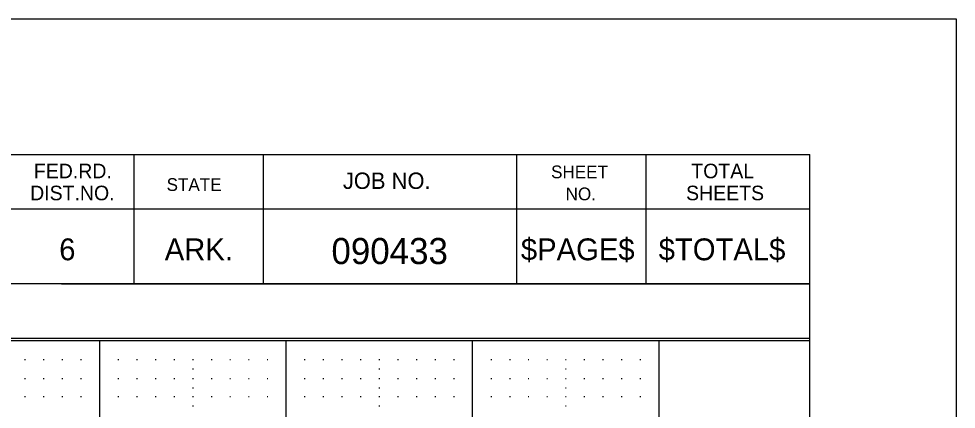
# Model space of a CAD drawing. Extents: x 0 to 34, y 0 to 22.
# Drawn here: x 28.97 to 34, y 19.9 to 22 of the extents above; entities that cross this region are included whole.
import ezdxf

# ---------------------------------------------------------------- set-up
doc = ezdxf.new("R2010")
doc.units = 0
for name, color, linetype in [('Level 1', 7, 'Continuous'), ('Level 4', 7, 'Continuous'), ('Level 5', 7, 'Continuous'), ('Level 63', 7, 'Continuous'), ('R_Border', 7, 'Continuous')]:
    doc.layers.add(name, color=color, linetype=linetype)

msp = doc.modelspace()

# ---------------------------------------------------------------- linework, layer by layer
at = {"layer": 'Level 1'}
for p, q in [((1.597, 21.272), (33.215, 21.272)), ((29.589, 21.2719), (29.589, 20.5779)), ((30.283, 21.2719), (30.283, 20.5779)), ((31.641, 21.2719), (31.641, 20.5779)), ((32.335, 21.2719), (32.335, 20.5779)), ((33.215, 0.726), (33.215, 21.272)), ((33.215, 20.9779), (28.905, 20.9779)), ((33.215, 20.9799), (33.215, 20.9799)), ((33.215, 20.5779), (28.905, 20.5779)), ((29.201, 20.5779), (33.215, 20.5779)), ((33.215, 20.2839), (26.951, 20.2839))]:
    msp.add_line(p, q, dxfattribs=at)
at = {"layer": 'Level 4'}
for p, q in [((33.215, 20.272), (1.597, 20.272)), ((29.406, 1.272), (29.406, 20.272)), ((30.406, 1.272), (30.406, 20.272)), ((31.406, 1.272), (31.406, 20.272)), ((32.406, 1.272), (32.406, 20.272))]:
    msp.add_line(p, q, dxfattribs=at)
at = {"layer": 'Level 5'}
for p, q in [((29.0035, 20.1705), (29.0085, 20.1705)), ((29.1035, 20.1705), (29.1085, 20.1705)), ((29.2035, 20.1705), (29.2085, 20.1705)), ((29.3035, 20.1705), (29.3085, 20.1705)), ((29.5035, 20.1705), (29.5085, 20.1705)), ((29.6035, 20.1705), (29.6085, 20.1705)), ((29.7035, 20.1705), (29.7085, 20.1705)), ((29.8035, 20.1705), (29.8085, 20.1705)), ((29.9035, 20.1705), (29.9085, 20.1705)), ((30.0035, 20.1705), (30.0085, 20.1705)), ((30.1035, 20.1705), (30.1085, 20.1705)), ((30.2035, 20.1705), (30.2085, 20.1705)), ((30.3035, 20.1705), (30.3085, 20.1705)), ((30.5035, 20.1705), (30.5085, 20.1705)), ((30.6035, 20.1705), (30.6085, 20.1705)), ((30.7035, 20.1705), (30.7085, 20.1705)), ((30.8035, 20.1705), (30.8085, 20.1705)), ((30.9035, 20.1705), (30.9085, 20.1705)), ((31.0035, 20.1705), (31.0085, 20.1705)), ((31.1035, 20.1705), (31.1085, 20.1705)), ((31.2035, 20.1705), (31.2085, 20.1705)), ((31.3035, 20.1705), (31.3085, 20.1705)), ((31.5035, 20.1705), (31.5085, 20.1705)), ((31.6035, 20.1705), (31.6085, 20.1705)), ((31.7035, 20.1705), (31.7085, 20.1705)), ((31.8035, 20.1705), (31.8085, 20.1705)), ((31.9035, 20.1705), (31.9085, 20.1705)), ((32.0035, 20.1705), (32.0085, 20.1705)), ((32.1035, 20.1705), (32.1085, 20.1705)), ((32.2035, 20.1705), (32.2085, 20.1705)), ((32.3035, 20.1705), (32.3085, 20.1705)), ((29.9035, 20.1205), (29.9085, 20.1205)), ((30.9035, 20.1205), (30.9085, 20.1205)), ((31.9035, 20.1205), (31.9085, 20.1205)), ((29.0035, 20.0691), (29.0085, 20.0691)), ((29.1035, 20.0691), (29.1085, 20.0691)), ((29.2035, 20.0691), (29.2085, 20.0691)), ((29.3035, 20.0691), (29.3085, 20.0691)), ((29.5035, 20.069), (29.5085, 20.069)), ((29.6035, 20.069), (29.6085, 20.069)), ((29.7035, 20.069), (29.7085, 20.069)), ((29.8035, 20.069), (29.8085, 20.069)), ((29.9035, 20.069), (29.9085, 20.069)), ((30.0035, 20.069), (30.0085, 20.069)), ((30.1035, 20.069), (30.1085, 20.069)), ((30.2035, 20.069), (30.2085, 20.069)), ((30.3035, 20.069), (30.3085, 20.069)), ((30.5035, 20.069), (30.5085, 20.069)), ((30.6035, 20.069), (30.6085, 20.069)), ((30.7035, 20.069), (30.7085, 20.069)), ((30.8035, 20.069), (30.8085, 20.069)), ((30.9035, 20.069), (30.9085, 20.069)), ((31.0035, 20.069), (31.0085, 20.069)), ((31.1035, 20.069), (31.1085, 20.069)), ((31.2035, 20.069), (31.2085, 20.069)), ((31.3035, 20.069), (31.3085, 20.069)), ((31.5035, 20.069), (31.5085, 20.069)), ((31.6035, 20.069), (31.6085, 20.069)), ((31.7035, 20.069), (31.7085, 20.069)), ((31.8035, 20.069), (31.8085, 20.069)), ((31.9035, 20.069), (31.9085, 20.069)), ((32.0035, 20.069), (32.0085, 20.069)), ((32.1035, 20.069), (32.1085, 20.069)), ((32.2035, 20.069), (32.2085, 20.069)), ((32.3035, 20.069), (32.3085, 20.069)), ((29.9035, 20.019), (29.9085, 20.019)), ((30.9035, 20.019), (30.9085, 20.019)), ((31.9035, 20.019), (31.9085, 20.019)), ((29.0035, 19.9722), (29.0085, 19.9722)), ((29.1035, 19.9722), (29.1085, 19.9722)), ((29.2035, 19.9722), (29.2085, 19.9722)), ((29.3035, 19.9722), (29.3085, 19.9722)), ((29.5035, 19.9722), (29.5085, 19.9722)), ((29.6035, 19.9722), (29.6085, 19.9722)), ((29.7035, 19.9722), (29.7085, 19.9722)), ((29.8035, 19.9722), (29.8085, 19.9722)), ((29.9035, 19.9722), (29.9085, 19.9722)), ((30.0035, 19.9722), (30.0085, 19.9722)), ((30.1035, 19.9722), (30.1085, 19.9722)), ((30.2035, 19.9722), (30.2085, 19.9722)), ((30.3035, 19.9722), (30.3085, 19.9722)), ((30.5035, 19.9722), (30.5085, 19.9722)), ((30.6035, 19.9722), (30.6085, 19.9722)), ((30.7035, 19.9722), (30.7085, 19.9722)), ((30.8035, 19.9722), (30.8085, 19.9722)), ((30.9035, 19.9722), (30.9085, 19.9722)), ((31.0035, 19.9722), (31.0085, 19.9722)), ((31.1035, 19.9722), (31.1085, 19.9722)), ((31.2035, 19.9722), (31.2085, 19.9722)), ((31.3035, 19.9722), (31.3085, 19.9722)), ((31.5035, 19.9722), (31.5085, 19.9722)), ((31.6035, 19.9722), (31.6085, 19.9722)), ((31.7035, 19.9722), (31.7085, 19.9722)), ((31.8035, 19.9722), (31.8085, 19.9722)), ((31.9035, 19.9722), (31.9085, 19.9722)), ((32.0035, 19.9722), (32.0085, 19.9722)), ((32.1035, 19.9722), (32.1085, 19.9722)), ((32.2035, 19.9722), (32.2085, 19.9722)), ((32.3035, 19.9722), (32.3085, 19.9722)), ((29.9035, 19.9222), (29.9085, 19.9222)), ((30.9035, 19.9222), (30.9085, 19.9222)), ((31.9035, 19.9222), (31.9085, 19.9222))]:
    msp.add_line(p, q, dxfattribs=at)
at = {"layer": 'Level 63'}
msp.add_lwpolyline([(0, 22), (34, 22), (34, 0), (0, 0)], close=True, dxfattribs=at)

# ---------------------------------------------------------------- texts
at = {"layer": 'Level 1'}
for s, height, p in [('FED.RD.', 0.07819, (29.053, 21.1439)), ('TOTAL', 0.07819, (32.579, 21.1439)), ('JOB NO.', 0.08792, (30.7104, 21.0868)), ('SHEET', 0.0684, (31.827, 21.1439)), ('STATE', 0.0684, (29.765, 21.0759)), ('DIST.NO.', 0.07819, (29.033, 21.0259)), ('NO.', 0.0684, (31.905, 21.0259)), ('SHEETS', 0.07819, (32.551, 21.0259)), ('6', 0.1172, (29.189, 20.7039)), ('ARK.', 0.11723, (29.755, 20.7039)), ('090433', 0.14, (30.649, 20.6834)), ('$PAGE$', 0.11724, (31.665, 20.7039)), ('$TOTAL$', 0.11724, (32.404, 20.7039))]:
    msp.add_text(s, height=height, dxfattribs=at).set_placement(p)
at = {"layer": 'R_Border'}
msp.add_text('JOB NO.', height=0.08792, dxfattribs=at).set_placement((30.7104, 21.0868))

doc.saveas('drawing.dxf')
